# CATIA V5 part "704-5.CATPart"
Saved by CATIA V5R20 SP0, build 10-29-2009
Part number: 704-5
Revision: TUTTO
Definition: NON CONOSCIUTO
Nomenclature: 704-5
Source: Unknown
Bounding box of the stored display mesh (mm): x -45 to 10, y -10 to 10, z 0 to 120
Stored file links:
  C:\Users\Utente\Desktop\IO LAVORO\3D X SITO CF\X SITO\704\704-5.CATPart
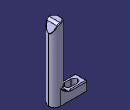
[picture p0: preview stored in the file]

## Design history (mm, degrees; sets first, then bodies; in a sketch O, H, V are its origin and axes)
Body1 "Importato1" (main body)
  Solid1: solid without history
